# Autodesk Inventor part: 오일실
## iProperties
Created: 2009-02
Part Number: 오일실
Material: 고무
Description: 오일-실
Document SubType Name: Modeling
Standard: KS B 2804
Designer: KYOUNG IL JANG
Standards Organization: KS
Language: ko-KR
Size Designation: S - 18 30 8
Categories: <MemberInstance><Categories><Category DisplayName="샤프트 부품" InternalName="7f7aeb1f-a693-4053-b835-cee3144e0d98" Mnemonic="SHFT"><Category DisplayName="실링" Intern
Density: 0.93 g/cm^3
Company: 한국ATC센터
IsCustomPart: 1
Author: KYOUNG IL JANG
